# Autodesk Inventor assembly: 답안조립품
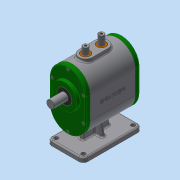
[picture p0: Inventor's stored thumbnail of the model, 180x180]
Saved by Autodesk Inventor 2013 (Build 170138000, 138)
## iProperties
Created: 2018-10
Part Number: 답안조립품
Document SubType Name: Assembly
Designer: Administrator
Author: Administrator
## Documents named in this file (15)
- C:\Users\Administrator\Desktop\381007V1025\답안조립품.iam
- C:\Users\Administrator\Desktop\381007V1025\본체.ipt
- C:\Users\Administrator\Desktop\381007V1025\가변스프링1.ipt
- C:\Users\Administrator\Desktop\381007V1025\가변스프링2.ipt
- C:\Users\Administrator\Desktop\381007V1025\뒤커버.ipt
- C:\Users\Administrator\Desktop\381007V1025\메인축.ipt
- C:\Users\Administrator\Desktop\381007V1025\베어링 608.ipt
- C:\Users\Administrator\Desktop\381007V1025\베어링 6003.ipt
- C:\Users\Administrator\Desktop\381007V1025\볼트 M4.ipt
- C:\Users\Administrator\Desktop\381007V1025\부시.ipt
- C:\Users\Administrator\Desktop\381007V1025\서브축.ipt
- C:\Users\Administrator\Desktop\381007V1025\슬라이더.ipt
- C:\Users\Administrator\Desktop\381007V1025\앞커버.ipt
- C:\Users\Administrator\Desktop\381007V1025\오일실 8 22 7.ipt
- C:\Users\Administrator\Desktop\381007V1025\오일실 17 32 8.ipt
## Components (2 placed, 2 different names)
1. 가변스프링1:1
2. 가변스프링2:1
